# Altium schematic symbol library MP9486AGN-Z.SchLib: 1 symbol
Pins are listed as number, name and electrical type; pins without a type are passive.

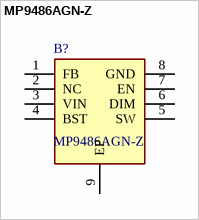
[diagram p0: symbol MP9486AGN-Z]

## MP9486AGN-Z
designator B?
Switching Voltage Regulators 100V Input, 3.5A, Switching Current Limit Step-Down Converter; Manufacturer_Name: Monolithic Power Systems (MPS); Geometry.Height: 1.7mm
footprint SOIC127P600X170-9N
pins: 1 FB, 2 NC, 3 VIN, 4 BST, 5 SW, 6 DIM, 7 EN, 8 GND, 9 EP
